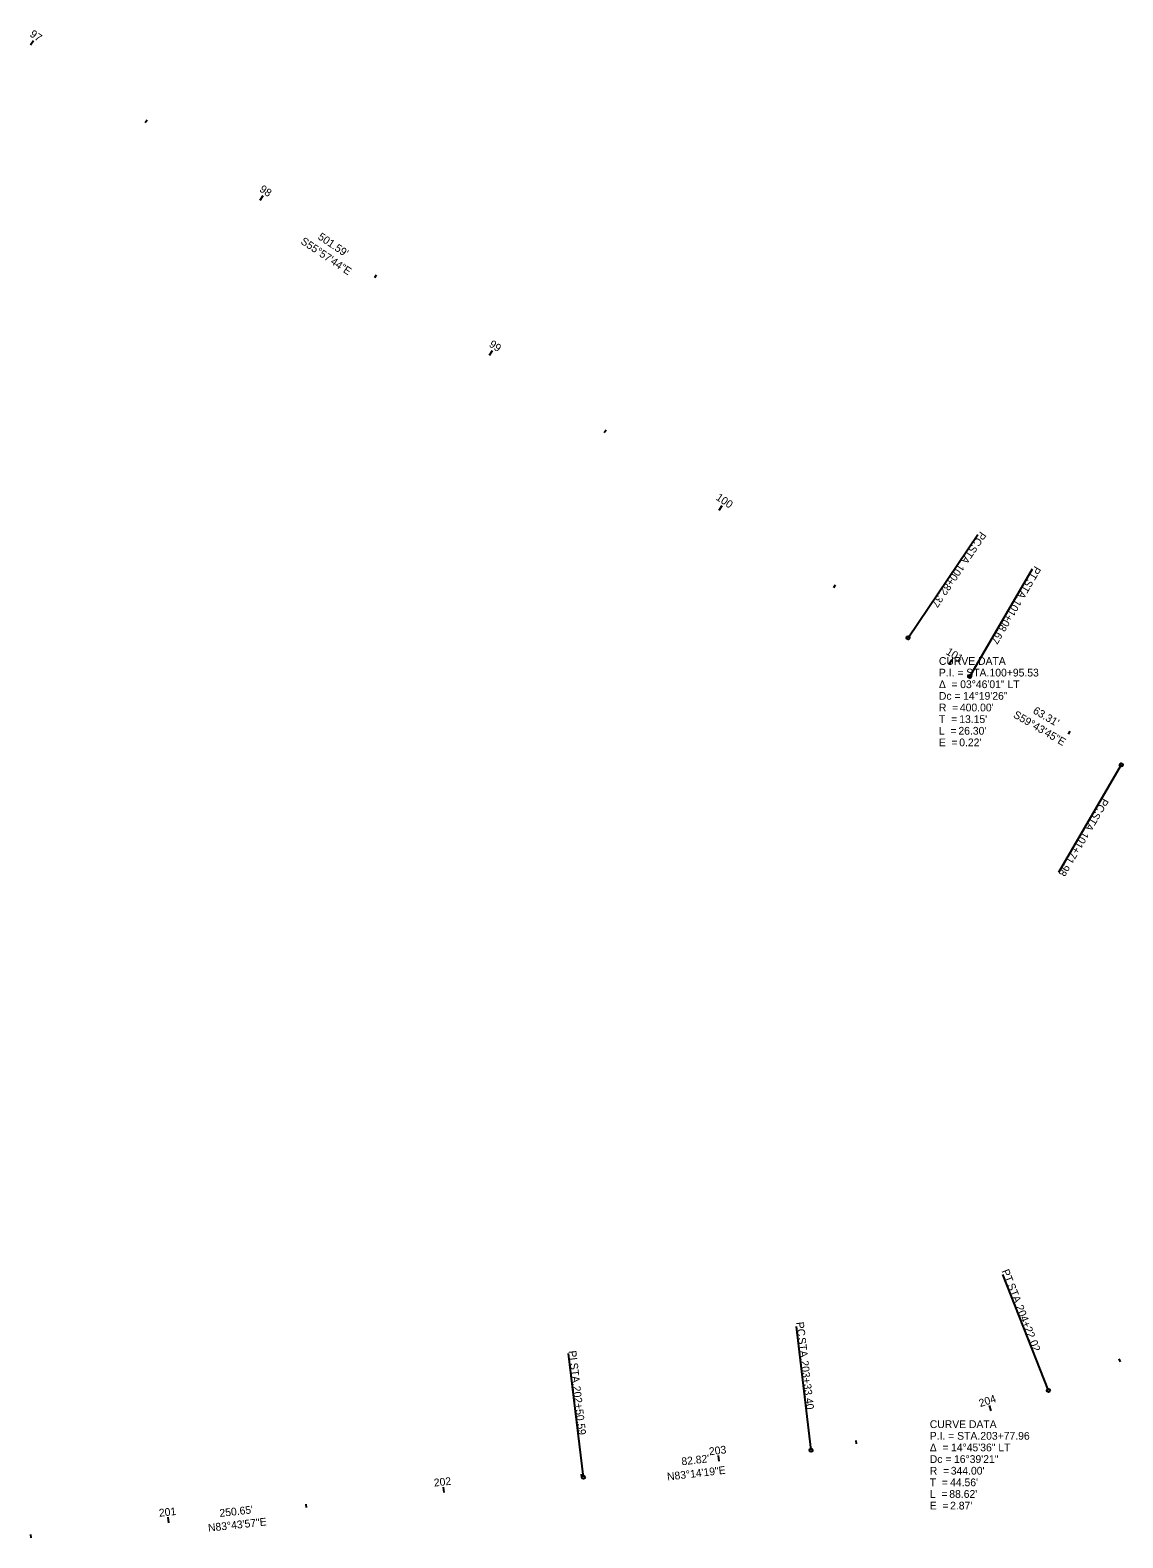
# Model space of a CAD drawing. Extents: x 1600023 to 1602131, y 285824 to 287284.
# Drawn here: x 1600456 to 1600850, y 286582 to 287126 of the extents above; entities that cross this region are included whole.
import ezdxf

# ---------------------------------------------------------------- set-up
doc = ezdxf.new("R2010")
doc.units = 0
for name, color, linetype in [('GE_P_Alignment_100_Bearings', 7, 'Continuous'), ('GE_P_Alignment_100_Cardinal_Points', 7, 'Continuous'), ('GE_P_Alignment_100_Curve_Data', 7, 'Continuous'), ('GE_P_Alignment_100_Distances', 7, 'Continuous'), ('GE_P_Alignment_100_Stations', 7, 'Continuous')]:
    doc.layers.add(name, color=color, linetype=linetype)

msp = doc.modelspace()

# ---------------------------------------------------------------- linework, layer by layer
at = {"layer": 'GE_P_Alignment_100_Cardinal_Points'}
for p, q in [((1600772.53, 286906.56), (1600797.72, 286943.85)), ((1600794.79, 286892.56), (1600817.48, 286931.43)), ((1600849.47, 286860.65), (1600826.79, 286821.79)), ((1600823.21, 286634.77), (1600806.71, 286676.63)), ((1600737.52, 286613.18), (1600732.22, 286657.87)), ((1600655.28, 286603.43), (1600649.98, 286648.12))]:
    msp.add_line(p, q, dxfattribs=at)
for centre in [(1600772.53, 286906.56), (1600794.79, 286892.56), (1600849.47, 286860.65), (1600823.21, 286634.77), (1600737.52, 286613.18), (1600655.28, 286603.43)]:
    msp.add_circle(centre, 0.6, dxfattribs=at)
at = {"layer": 'GE_P_Alignment_100_Stations'}
for p, q in [((1600455.67, 287120.59), (1600456.79, 287122.24)), ((1600497.1, 287092.6), (1600497.78, 287093.59)), ((1600538.54, 287064.61), (1600539.66, 287066.27)), ((1600579.97, 287036.63), (1600580.64, 287037.62)), ((1600621.4, 287008.64), (1600622.52, 287010.3)), ((1600662.84, 286980.65), (1600663.51, 286981.65)), ((1600704.27, 286952.66), (1600705.39, 286954.32)), ((1600745.7, 286924.68), (1600746.38, 286925.67)), ((1600787.35, 286897.02), (1600788.4, 286898.72)), ((1600830.49, 286871.73), (1600831.09, 286872.77)), ((1600849.25, 286645.03), (1600848.8, 286646.15)), ((1600802.49, 286627.35), (1600801.87, 286629.26)), ((1600753.95, 286615.53), (1600753.75, 286616.71)), ((1600704.35, 286609.25), (1600704.12, 286611.23)), ((1600654.7, 286603.36), (1600654.57, 286604.56)), ((1600605, 286597.91), (1600604.78, 286599.89)), ((1600555.3, 286592.45), (1600555.17, 286593.64)), ((1600505.59, 286586.99), (1600505.38, 286588.98)), ((1600455.89, 286581.53), (1600455.76, 286582.72))]:
    msp.add_line(p, q, dxfattribs=at)

# ---------------------------------------------------------------- texts
at = {"layer": 'GE_P_Alignment_100_Bearings'}
for s, rotation, p in [('S55°57\'44"E', 325.9623, (1600552.95, 287049.08)), ('S59°43\'45"E', 329.7293, (1600810.26, 286877.98)), ('N83°14\'19"E', 6.7614, (1600685.68, 286602.2)), ('N83°43\'57"E', 6.2675, (1600519.93, 286583.73))]:
    msp.add_text(s, height=2.8, rotation=rotation, dxfattribs=at).set_placement(p)
at = {"layer": 'GE_P_Alignment_100_Cardinal_Points'}
for s, rotation, p in [('PC', 235.9623, (1600798.63, 286945.12)), (' STA. ', 235.9623, (1600796.06, 286941.32)), ('100+82.37', 235.9623, (1600790.77, 286933.49)), ('PT', 239.7293, (1600818.26, 286932.68)), (' STA. ', 239.7293, (1600816.03, 286928.87)), ('101+08.67', 239.7293, (1600811.27, 286920.71)), ('PC', 239.7293, (1600842.69, 286848.95)), (' STA. ', 239.7293, (1600840.38, 286844.99)), ('101+71.98', 239.7293, (1600835.61, 286836.83)), ('PT', 291.5214, (1600806.25, 286677.89)), (' STA. ', 291.5214, (1600807.87, 286673.79)), ('204+22.02', 291.5214, (1600811.34, 286664.99)), ('PC', 276.7614, (1600732.09, 286659.35)), (' STA. ', 276.7614, (1600732.63, 286654.8)), ('PI', 276.7614, (1600649.92, 286648.98)), (' STA. ', 276.7614, (1600650.32, 286645.61)), ('203+33.40', 276.7614, (1600733.74, 286645.41)), ('202+50.59', 276.7614, (1600651.43, 286636.23))]:
    msp.add_text(s, height=2.8, rotation=rotation, dxfattribs=at).set_placement(p)
at = {"layer": 'GE_P_Alignment_100_Curve_Data'}
for s, p in [('CURVE DATA', (1600783.66, 286896.76)), ('P.I. = STA. ', (1600783.66, 286892.56)), ('100+95.53', (1600801.93, 286892.56)), ('Δ  = ', (1600783.66, 286888.36)), ('Dc = ', (1600783.66, 286884.16)), ('03°46\'01" LT', (1600791.34, 286888.36)), ('14°19\'26"', (1600792.4, 286884.16)), ('R  = ', (1600783.66, 286879.96)), ("400.00'", (1600791.24, 286879.96)), ('T  = ', (1600783.66, 286875.76)), ("13.15'", (1600791, 286875.76)), ('L  = ', (1600783.66, 286871.56)), ('E  = ', (1600783.66, 286867.36)), ("26.30'", (1600790.7, 286871.56)), ("0.22'", (1600791, 286867.36)), ('CURVE DATA', (1600780.37, 286621.17)), ('P.I. = STA. ', (1600780.37, 286616.97)), ('203+77.96', (1600798.63, 286616.97)), ('Δ  = ', (1600780.37, 286612.77)), ('14°45\'36" LT', (1600788.04, 286612.77)), ('Dc = ', (1600780.37, 286608.57)), ('16°39\'21"', (1600789.11, 286608.57)), ('R  = ', (1600780.37, 286604.37)), ("44.56'", (1600787.7, 286600.17)), ("344.00'", (1600787.95, 286604.37)), ('T  = ', (1600780.37, 286600.17)), ('L  = ', (1600780.37, 286595.97)), ("88.62'", (1600787.41, 286595.97)), ('E  = ', (1600780.37, 286591.77)), ("2.87'", (1600787.71, 286591.77))]:
    msp.add_text(s, height=2.8, dxfattribs=at).set_placement(p)
at = {"layer": 'GE_P_Alignment_100_Distances'}
for s, rotation, p in [("501.59'", 325.9623, (1600559.19, 287050.71)), ("63.31'", 329.7293, (1600817.35, 286879.45)), ("82.82'", 6.7614, (1600690.87, 286607.69)), ("250.65'", 6.2675, (1600524.06, 286589.06))]:
    msp.add_text(s, height=2.8, rotation=rotation, dxfattribs=at).set_placement(p)
at = {"layer": 'GE_P_Alignment_100_Stations'}
for s, rotation, p in [('97', 325.9623, (1600455.16, 287123.94)), ('98', 325.9623, (1600538.1, 287067.93)), ('99', 325.9623, (1600620.98, 287011.94)), ('100', 325.9623, (1600702.9, 286956.61)), ('101', 328.4871, (1600785.97, 286900.79)), ('204', 17.854, (1600798.61, 286628.73)), ('203', 6.7614, (1600700.81, 286611.34)), ('202', 6.2675, (1600601.46, 286600.03)), ('201', 6.2675, (1600502.19, 286589.13))]:
    msp.add_text(s, height=2.8, rotation=rotation, dxfattribs=at).set_placement(p)

doc.saveas('drawing.dxf')
